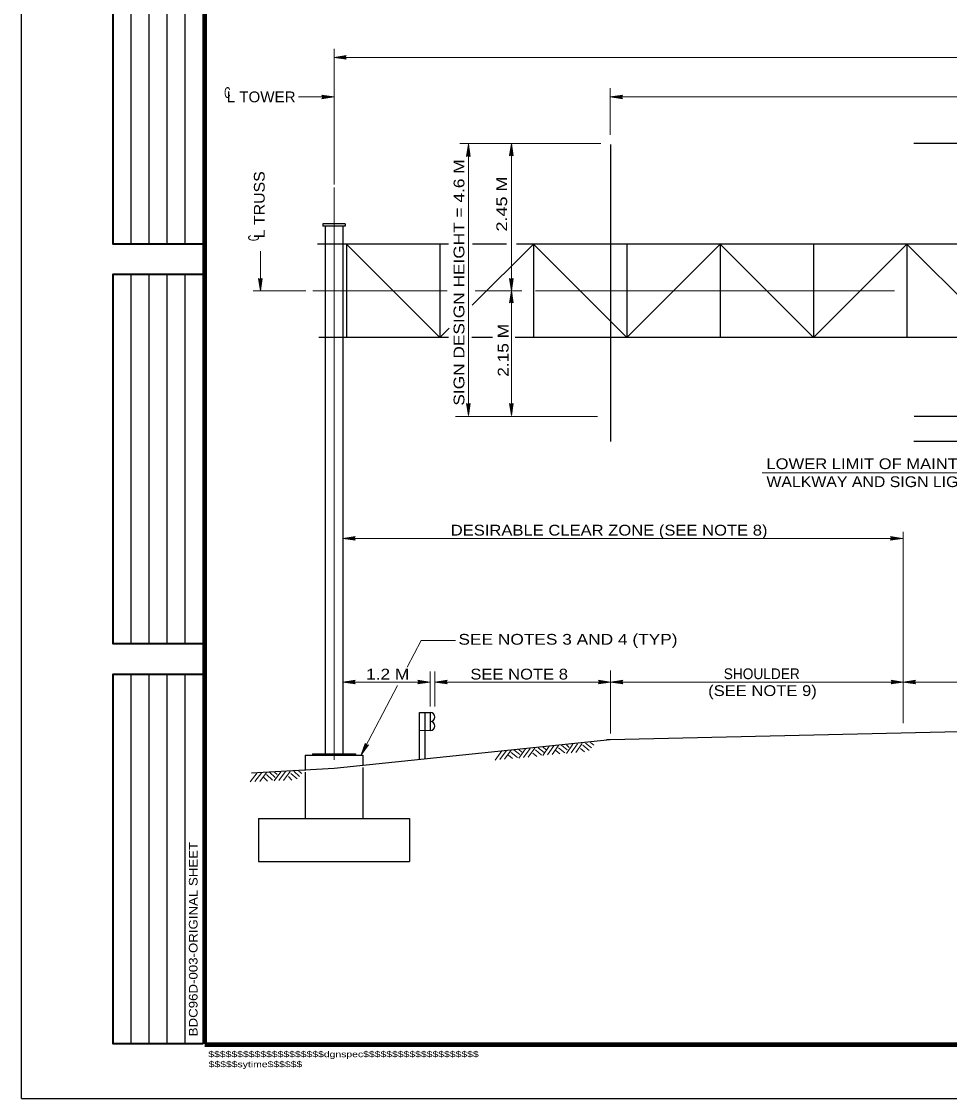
# Model space of a CAD drawing. Extents: x 312601.858 to 312602.699, y 144420.127 to 144420.721.
# Drawn here: x 312601.8578 to 312602.1162, y 144420.1268 to 144420.4268 of the extents above; entities that cross this region are included whole.
import ezdxf
from ezdxf.enums import TextEntityAlignment as Align

# ---------------------------------------------------------------- set-up
doc = ezdxf.new("R2010")
doc.units = 0
doc.header["$LTSCALE"] = 0.0012
doc.linetypes.add('DOT_DASHED', pattern=[7.7, 5, -1.2, 0.3, -1.2])
doc.linetypes.add('LONG_DASHED', pattern=[7.5, 6, -1.5])
for name, color, linetype, lineweight in [('1', 7, 'Continuous', 13), ('2', 7, 'Continuous', 13), ('39', 7, 'Continuous', 13), ('60', 7, 'Continuous', 25)]:
    doc.layers.add(name, color=color, linetype=linetype, lineweight=lineweight)

msp = doc.modelspace()

# ---------------------------------------------------------------- hatches: boundary and pattern name
at = {"layer": '39'}
for points in [[(312601.9479, 144420.4168), (312601.9482, 144420.4163), (312601.9448, 144420.4168), (312601.9482, 144420.4173)], [(312601.9417, 144420.4058), (312601.9414, 144420.4063), (312601.9448, 144420.4058), (312601.9414, 144420.4053)], [(312602.0248, 144420.4058), (312602.0251, 144420.4053), (312602.0217, 144420.4058), (312602.0251, 144420.4063)], [(312601.9822, 144420.3895), (312601.9817, 144420.3892), (312601.9822, 144420.3926), (312601.9827, 144420.3892)], [(312601.9822, 144420.3895), (312601.9817, 144420.3892), (312601.9822, 144420.3926), (312601.9827, 144420.3892)], [(312601.9942, 144420.3897), (312601.9937, 144420.3894), (312601.9942, 144420.3928), (312601.9947, 144420.3894)], [(312601.9942, 144420.3897), (312601.9937, 144420.3894), (312601.9942, 144420.3928), (312601.9947, 144420.3894)], [(312601.9243, 144420.3549), (312601.9248, 144420.3552), (312601.9243, 144420.3518), (312601.9238, 144420.3552)], [(312601.9942, 144420.3549), (312601.9947, 144420.3552), (312601.9942, 144420.3518), (312601.9937, 144420.3552)], [(312601.9942, 144420.3487), (312601.9937, 144420.3484), (312601.9942, 144420.3518), (312601.9947, 144420.3484)], [(312601.9822, 144420.3201), (312601.9827, 144420.3204), (312601.9822, 144420.317), (312601.9817, 144420.3204)], [(312601.9822, 144420.3201), (312601.9827, 144420.3204), (312601.9822, 144420.317), (312601.9817, 144420.3204)], [(312601.9942, 144420.3201), (312601.9947, 144420.3204), (312601.9942, 144420.317), (312601.9937, 144420.3204)], [(312601.9942, 144420.3201), (312601.9947, 144420.3204), (312601.9942, 144420.317), (312601.9937, 144420.3204)], [(312601.9504, 144420.2828), (312601.9507, 144420.2823), (312601.9473, 144420.2828), (312601.9507, 144420.2833)], [(312602.1, 144420.2828), (312602.0997, 144420.2833), (312602.1031, 144420.2828), (312602.0997, 144420.2823)], [(312602.1, 144420.2828), (312602.0997, 144420.2833), (312602.1031, 144420.2828), (312602.0997, 144420.2823)], [(312601.9504, 144420.2428), (312601.9507, 144420.2423), (312601.9473, 144420.2428), (312601.9507, 144420.2433)], [(312601.9684, 144420.2428), (312601.9681, 144420.2433), (312601.9715, 144420.2428), (312601.9681, 144420.2423)], [(312601.976, 144420.2428), (312601.9763, 144420.2423), (312601.9729, 144420.2428), (312601.9763, 144420.2433)], [(312602.0187, 144420.2428), (312602.0184, 144420.2433), (312602.0218, 144420.2428), (312602.0184, 144420.2423)], [(312602.0249, 144420.2428), (312602.0252, 144420.2423), (312602.0218, 144420.2428), (312602.0252, 144420.2433)], [(312602.1002, 144420.2428), (312602.0999, 144420.2433), (312602.1033, 144420.2428), (312602.0999, 144420.2423)], [(312602.1064, 144420.2428), (312602.1067, 144420.2423), (312602.1033, 144420.2428), (312602.1067, 144420.2433)], [(312601.9538, 144420.2252), (312601.9544, 144420.2253), (312601.9524, 144420.2225), (312601.9535, 144420.2257)]]:
    msp.add_hatch(color=256, dxfattribs=at).paths.add_polyline_path(points)

# ---------------------------------------------------------------- linework, layer by layer
at = {"layer": '1'}
for p, q in [((312601.9976, 144420.2218), (312601.9994, 144420.2243)), ((312601.9989, 144420.2219), (312602.0007, 144420.2244)), ((312602.0016, 144420.2245), (312602.0033, 144420.2232)), ((312602.0029, 144420.2223), (312602.0047, 144420.2249)), ((312602.003, 144420.2247), (312602.0039, 144420.2239)), ((312602.0042, 144420.2225), (312602.006, 144420.225)), ((312602.0055, 144420.2226), (312602.0073, 144420.2251)), ((312602.0073, 144420.2245), (312602.0091, 144420.2231)), ((312602.0081, 144420.2252), (312602.0097, 144420.2239)), ((312602.0095, 144420.2229), (312602.0113, 144420.2255)), ((312602.0095, 144420.2253), (312602.0103, 144420.2246)), ((312602.0108, 144420.2231), (312602.0126, 144420.2256)), ((312602.0121, 144420.2232), (312602.0139, 144420.2257)), ((312602.0134, 144420.2243), (312602.0145, 144420.2234)), ((312602.0141, 144420.2252), (312602.0158, 144420.2237)), ((312602.0148, 144420.2258), (312602.0165, 144420.2245)), ((312602.0162, 144420.226), (312602.0171, 144420.2252)), ((312601.9897, 144420.221), (312601.9915, 144420.2236)), ((312601.991, 144420.2212), (312601.9928, 144420.2237)), ((312601.9923, 144420.2213), (312601.9941, 144420.2238)), ((312601.9934, 144420.2224), (312601.9945, 144420.2215)), ((312601.9941, 144420.2232), (312601.9959, 144420.2218)), ((312601.9949, 144420.2239), (312601.9965, 144420.2226)), ((312601.9963, 144420.2216), (312601.9981, 144420.2242)), ((312601.9963, 144420.224), (312601.9971, 144420.2233)), ((312602.0002, 144420.223), (312602.0013, 144420.2221)), ((312602.0009, 144420.2239), (312602.0026, 144420.2224)), ((312602.0066, 144420.2237), (312602.0077, 144420.2228)), ((312601.9215, 144420.215), (312601.9234, 144420.2175)), ((312601.9228, 144420.2151), (312601.9247, 144420.2176)), ((312601.9241, 144420.2151), (312601.926, 144420.2176)), ((312601.9253, 144420.2162), (312601.9263, 144420.2152)), ((312601.926, 144420.217), (312601.9277, 144420.2155)), ((312601.9268, 144420.2177), (312601.9284, 144420.2162)), ((312601.9281, 144420.2153), (312601.93, 144420.2178)), ((312601.9282, 144420.2177), (312601.929, 144420.217)), ((312601.9294, 144420.2154), (312601.9313, 144420.2179)), ((312601.9307, 144420.2154), (312601.9326, 144420.2179)), ((312601.9321, 144420.2165), (312601.9331, 144420.2155)), ((312601.9328, 144420.2173), (312601.9345, 144420.2158)), ((312601.9336, 144420.218), (312601.9352, 144420.2165)), ((312601.935, 144420.218), (312601.9358, 144420.2173))]:
    msp.add_line(p, q, dxfattribs=at)
at = {"layer": '2'}
msp.add_line((312601.9243, 144420.3518), (312601.9243, 144420.3628), dxfattribs=at)
msp.add_lwpolyline([(312602.064, 144420.3011), (312602.14, 144420.3011), (312602.14, 144420.3098)], dxfattribs=at)
at = {"layer": '39', "lineweight": 25}
for p, q in [((312601.8578, 144420.1268), (312601.8578, 144420.7208)), ((312601.9479, 144420.3704), (312601.9417, 144420.3704)), ((312601.9417, 144420.3704), (312601.9417, 144420.3698)), ((312601.9479, 144420.3698), (312601.9417, 144420.3698)), ((312601.9479, 144420.3704), (312601.9479, 144420.3698)), ((312601.9767, 144420.3648), (312601.9402, 144420.3648)), ((312601.9483, 144420.3648), (312601.9483, 144420.3388)), ((312601.9743, 144420.3388), (312601.9483, 144420.3648)), ((312601.9743, 144420.3648), (312601.9743, 144420.3388)), ((312601.9833, 144420.3478), (312602.0003, 144420.3648)), ((312601.9928, 144420.3648), (312601.9834, 144420.3648)), ((312602.475, 144420.3648), (312601.9956, 144420.3648)), ((312602.0003, 144420.3648), (312602.0003, 144420.3388)), ((312602.0263, 144420.3388), (312602.0003, 144420.3648)), ((312602.0263, 144420.3648), (312602.0263, 144420.3388)), ((312602.0263, 144420.3388), (312602.0523, 144420.3648)), ((312602.0523, 144420.3648), (312602.0523, 144420.3388)), ((312602.0783, 144420.3388), (312602.0523, 144420.3648)), ((312602.0783, 144420.3648), (312602.0783, 144420.3388)), ((312602.0783, 144420.3388), (312602.1043, 144420.3648)), ((312602.1043, 144420.3648), (312602.1043, 144420.3388)), ((312602.1303, 144420.3388), (312602.1043, 144420.3648)), ((312601.9743, 144420.3388), (312601.9769, 144420.3414)), ((312601.9767, 144420.3388), (312601.9406, 144420.3388)), ((312601.9889, 144420.3388), (312601.9832, 144420.3388)), ((312602.4756, 144420.3388), (312601.9952, 144420.3388)), ((312601.9686, 144420.2213), (312601.9686, 144420.2343)), ((312601.9701, 144420.2343), (312601.9701, 144420.2214)), ((312602.0217, 144420.2268), (312602.207, 144420.231)), ((312601.9368, 144420.2224), (312601.9528, 144420.2224)), ((312601.9368, 144420.2224), (312601.9368, 144420.2182)), ((312601.9388, 144420.2228), (312601.9508, 144420.2228)), ((312601.9388, 144420.2228), (312601.9388, 144420.2224)), ((312601.9423, 144420.2228), (312601.9508, 144420.2228)), ((312601.9508, 144420.2228), (312601.9508, 144420.2224)), ((312601.9528, 144420.2224), (312601.9528, 144420.2196)), ((312601.8578, 144420.1268), (312602.6988, 144420.1268))]:
    msp.add_line(p, q, dxfattribs=at)
at = {"layer": '39', "lineweight": 158}
for p, q in [((312601.9088, 144420.142), (312601.9088, 144420.6818)), ((312601.9088, 144420.1418), (312602.6838, 144420.1418))]:
    msp.add_line(p, q, dxfattribs=at)
at = {"layer": '39'}
for p, q in [((312601.9448, 144420.4192), (312601.9448, 144420.3814)), ((312602.4718, 144420.4168), (312601.9448, 144420.4168)), ((312602.0217, 144420.4082), (312602.0217, 144420.3952)), ((312601.9448, 144420.4058), (312601.9349, 144420.4058)), ((312602.4062, 144420.4058), (312602.0217, 144420.4058)), ((312602.0191, 144420.3928), (312601.9798, 144420.3928)), ((312601.9822, 144420.317), (312601.9822, 144420.3926)), ((312602.0263, 144420.3388), (312602.0003, 144420.3648)), ((312602.0263, 144420.3388), (312602.0003, 144420.3648)), ((312602.0263, 144420.3388), (312602.0003, 144420.3648)), ((312602.0263, 144420.3388), (312602.0523, 144420.3648)), ((312602.0263, 144420.3388), (312602.0523, 144420.3648)), ((312602.0783, 144420.3388), (312602.1043, 144420.3648)), ((312602.0783, 144420.3388), (312602.1043, 144420.3648)), ((312601.9223, 144420.3518), (312601.937, 144420.3518)), ((312601.9841, 144420.3518), (312601.9971, 144420.3518)), ((312602.0182, 144420.3168), (312601.9786, 144420.3168)), ((312602.1033, 144420.2846), (312602.1033, 144420.2313)), ((312601.9473, 144420.2828), (312602.1031, 144420.2828)), ((312601.9691, 144420.2544), (312601.9652, 144420.2469)), ((312601.9786, 144420.2544), (312601.9691, 144420.2544)), ((312601.9716, 144420.2457), (312601.9716, 144420.236)), ((312601.9729, 144420.2457), (312601.9729, 144420.236)), ((312602.0218, 144420.246), (312602.0218, 144420.2285)), ((312601.9473, 144420.2428), (312601.9716, 144420.2428)), ((312601.9729, 144420.2428), (312602.0218, 144420.2428)), ((312601.9625, 144420.2418), (312601.9524, 144420.2225)), ((312601.9701, 144420.2343), (312601.9701, 144420.2213)), ((312601.9448, 144420.232), (312601.9448, 144420.2211)), ((312601.9686, 144420.2293), (312601.9716, 144420.2293)), ((312601.9686, 144420.2293), (312601.9716, 144420.2293)), ((312602.0207, 144420.2268), (312602.0242, 144420.2268))]:
    msp.add_line(p, q, dxfattribs=at)
at = {"layer": '39', "linetype": 'LONG_DASHED', "lineweight": 25}
for p, q in [((312602.4062, 144420.3928), (312602.0218, 144420.3928)), ((312602.0218, 144420.3925), (312602.0218, 144420.3098)), ((312602.4063, 144420.3168), (312602.0218, 144420.3168)), ((312602.4062, 144420.3098), (312602.0218, 144420.3098)), ((312601.9528, 144420.219), (312601.9528, 144420.2048)), ((312601.9368, 144420.2177), (312601.9368, 144420.2048)), ((312601.9238, 144420.2048), (312601.9658, 144420.2048)), ((312601.9238, 144420.2048), (312601.9238, 144420.1928)), ((312601.9658, 144420.2048), (312601.9658, 144420.1928)), ((312601.9238, 144420.1928), (312601.9658, 144420.1928))]:
    msp.add_line(p, q, dxfattribs=at)
at = {"layer": '39', "linetype": 'DOT_DASHED'}
for p, q in [((312601.9448, 144420.3806), (312601.9448, 144420.3059)), ((312601.9389, 144420.3518), (312601.9763, 144420.3518)), ((312602.0009, 144420.3518), (312602.4896, 144420.3518)), ((312601.9448, 144420.306), (312601.9448, 144420.232))]:
    msp.add_line(p, q, dxfattribs=at)
at = {"layer": '39'}
for points in [[(312601.9479, 144420.4168), (312601.9482, 144420.4163), (312601.9448, 144420.4168), (312601.9482, 144420.4173)], [(312601.9417, 144420.4058), (312601.9414, 144420.4063), (312601.9448, 144420.4058), (312601.9414, 144420.4053)], [(312602.0248, 144420.4058), (312602.0251, 144420.4053), (312602.0217, 144420.4058), (312602.0251, 144420.4063)], [(312601.9822, 144420.3895), (312601.9817, 144420.3892), (312601.9822, 144420.3926), (312601.9827, 144420.3892)], [(312601.9822, 144420.3895), (312601.9817, 144420.3892), (312601.9822, 144420.3926), (312601.9827, 144420.3892)], [(312601.9942, 144420.3897), (312601.9937, 144420.3894), (312601.9942, 144420.3928), (312601.9947, 144420.3894)], [(312601.9942, 144420.3897), (312601.9937, 144420.3894), (312601.9942, 144420.3928), (312601.9947, 144420.3894)], [(312601.9243, 144420.3549), (312601.9248, 144420.3552), (312601.9243, 144420.3518), (312601.9238, 144420.3552)], [(312601.9942, 144420.3549), (312601.9947, 144420.3552), (312601.9942, 144420.3518), (312601.9937, 144420.3552)], [(312601.9942, 144420.3487), (312601.9937, 144420.3484), (312601.9942, 144420.3518), (312601.9947, 144420.3484)], [(312601.9822, 144420.3201), (312601.9827, 144420.3204), (312601.9822, 144420.317), (312601.9817, 144420.3204)], [(312601.9822, 144420.3201), (312601.9827, 144420.3204), (312601.9822, 144420.317), (312601.9817, 144420.3204)], [(312601.9942, 144420.3201), (312601.9947, 144420.3204), (312601.9942, 144420.317), (312601.9937, 144420.3204)], [(312601.9942, 144420.3201), (312601.9947, 144420.3204), (312601.9942, 144420.317), (312601.9937, 144420.3204)], [(312601.9504, 144420.2828), (312601.9507, 144420.2823), (312601.9473, 144420.2828), (312601.9507, 144420.2833)], [(312602.1, 144420.2828), (312602.0997, 144420.2833), (312602.1031, 144420.2828), (312602.0997, 144420.2823)], [(312602.1, 144420.2828), (312602.0997, 144420.2833), (312602.1031, 144420.2828), (312602.0997, 144420.2823)], [(312601.9504, 144420.2428), (312601.9507, 144420.2423), (312601.9473, 144420.2428), (312601.9507, 144420.2433)], [(312601.9684, 144420.2428), (312601.9681, 144420.2433), (312601.9715, 144420.2428), (312601.9681, 144420.2423)], [(312601.976, 144420.2428), (312601.9763, 144420.2423), (312601.9729, 144420.2428), (312601.9763, 144420.2433)], [(312602.0187, 144420.2428), (312602.0184, 144420.2433), (312602.0218, 144420.2428), (312602.0184, 144420.2423)], [(312602.0249, 144420.2428), (312602.0252, 144420.2423), (312602.0218, 144420.2428), (312602.0252, 144420.2433)], [(312602.1002, 144420.2428), (312602.0999, 144420.2433), (312602.1033, 144420.2428), (312602.0999, 144420.2423)], [(312602.1064, 144420.2428), (312602.1067, 144420.2423), (312602.1033, 144420.2428), (312602.1067, 144420.2433)], [(312601.9538, 144420.2252), (312601.9544, 144420.2253), (312601.9524, 144420.2225), (312601.9535, 144420.2257)]]:
    msp.add_lwpolyline(points, close=True, dxfattribs=at)
for points in [[(312601.9942, 144420.317), (312601.9942, 144420.3518), (312601.9942, 144420.3928)], [(312602.0218, 144420.2428), (312602.1033, 144420.2428), (312602.1703, 144420.2428), (312602.3093, 144420.2428), (312602.4063, 144420.2428)], [(312601.9686, 144420.2343), (312601.9716, 144420.2343), (312601.9716, 144420.2293)]]:
    msp.add_lwpolyline(points, dxfattribs=at)
at = {"layer": '39', "lineweight": 25}
for points in [[(312601.9423, 144420.3698), (312601.9423, 144420.2269), (312601.9423, 144420.2228)], [(312601.9473, 144420.3698), (312601.9473, 144420.2272), (312601.9473, 144420.2228)], [(312601.9686, 144420.2343), (312601.9716, 144420.2343), (312601.9716, 144420.2293)], [(312601.9218, 144420.2175), (312601.9448, 144420.2188), (312602.0217, 144420.2268)]]:
    msp.add_lwpolyline(points, dxfattribs=at)
for centre in [(312601.9716, 144420.23305), (312601.9716, 144420.23055)]:
    msp.add_arc(centre, 0.00125, 270, 90, dxfattribs=at)
at = {"layer": '39'}
for centre in [(312601.9716, 144420.23305), (312601.9716, 144420.23055)]:
    msp.add_arc(centre, 0.00125, 270, 90, dxfattribs=at)
at = {"layer": '60'}
for p, q in [((312601.8883, 144420.3648), (312601.8883, 144420.4678)), ((312601.8933, 144420.3648), (312601.8933, 144420.4678)), ((312601.8983, 144420.3648), (312601.8983, 144420.4678)), ((312601.9034, 144420.3648), (312601.9034, 144420.4678)), ((312601.8883, 144420.2534), (312601.8883, 144420.3564)), ((312601.8933, 144420.2534), (312601.8933, 144420.3564)), ((312601.8983, 144420.2534), (312601.8983, 144420.3564)), ((312601.9034, 144420.2534), (312601.9034, 144420.3564)), ((312601.8883, 144420.142), (312601.8883, 144420.245)), ((312601.8933, 144420.142), (312601.8933, 144420.245)), ((312601.8983, 144420.142), (312601.8983, 144420.245)), ((312601.9034, 144420.142), (312601.9034, 144420.245))]:
    msp.add_line(p, q, dxfattribs=at)
at = {"layer": '60', "lineweight": 35}
for points in [[(312601.9084, 144420.3648), (312601.8833, 144420.3648), (312601.8833, 144420.4678), (312601.9084, 144420.4678)], [(312601.9084, 144420.2534), (312601.8833, 144420.2534), (312601.8833, 144420.3564), (312601.9084, 144420.3564)], [(312601.9084, 144420.142), (312601.8833, 144420.142), (312601.8833, 144420.245), (312601.9084, 144420.245)]]:
    msp.add_lwpolyline(points, dxfattribs=at)

# ---------------------------------------------------------------- texts
at = {"layer": '2'}
for s, width, p in [('C', 0.6, (312601.9151, 144420.4055)), ('L TOWER', 1.05, (312601.9245, 144420.4043)), ('1.2 M', 1.2, (312601.95975, 144420.2435)), ('(SEE NOTE 9)', 1.15, (312602.0641, 144420.2389))]:
    msp.add_text(s, height=0.003, dxfattribs=dict(at, width=width)).set_placement(p, align=Align.CENTER)
for s, height, width, p in [('SIGN DESIGN HEIGHT = 4.6 M', 0.003, 1.2, (312601.9811, 144420.3541)), ('L TRUSS', 0.003, 1.1, (312601.9255, 144420.37575)), ('2.45 M', 0.003, 1.25, (312601.993, 144420.37595)), ('C', 0.003, 0.6, (312601.9239, 144420.3665)), ('2.15 M', 0.003, 1.2, (312601.9934, 144420.3352)), ('BDC96D-003-ORIGINAL SHEET', 0.0024, 1.15, (312601.9068, 144420.1712))]:
    msp.add_text(s, height=height, rotation=90, dxfattribs=dict(at, width=width)).set_placement(p, align=Align.CENTER)
for s, height, width, p in [('LOWER LIMIT OF MAINTENANCE', 0.003, 1.15, (312602.0652, 144420.3021)), ('WALKWAY AND SIGN LIGHTING', 0.003, 1.1, (312602.0652, 144420.2971)), ('$$$$$$$$$$$$$$$$$$$$dgnspec$$$$$$$$$$$$$$$$$$$$', 0.001664, 1.3, (312601.9098, 144420.1383)), ('$$$$$sytime$$$$$$', 0.001664, 1.3, (312601.9099, 144420.1355))]:
    msp.add_text(s, height=height, dxfattribs=dict(at, width=width)).set_placement(p)
at = {"layer": '39'}
for s, width, p in [('DESIRABLE CLEAR ZONE (SEE NOTE 8)', 1.15, (312602.0214, 144420.2836)), ('SEE NOTES 3 AND 4 (TYP)', 1.2, (312602.00995, 144420.2532)), ('SEE NOTE 8', 1.15, (312601.99635, 144420.2435)), ('SHOULDER', 0.95, (312602.0639, 144420.2436))]:
    msp.add_text(s, height=0.003, dxfattribs=dict(at, width=width)).set_placement(p, align=Align.CENTER)

doc.saveas('drawing.dxf')
